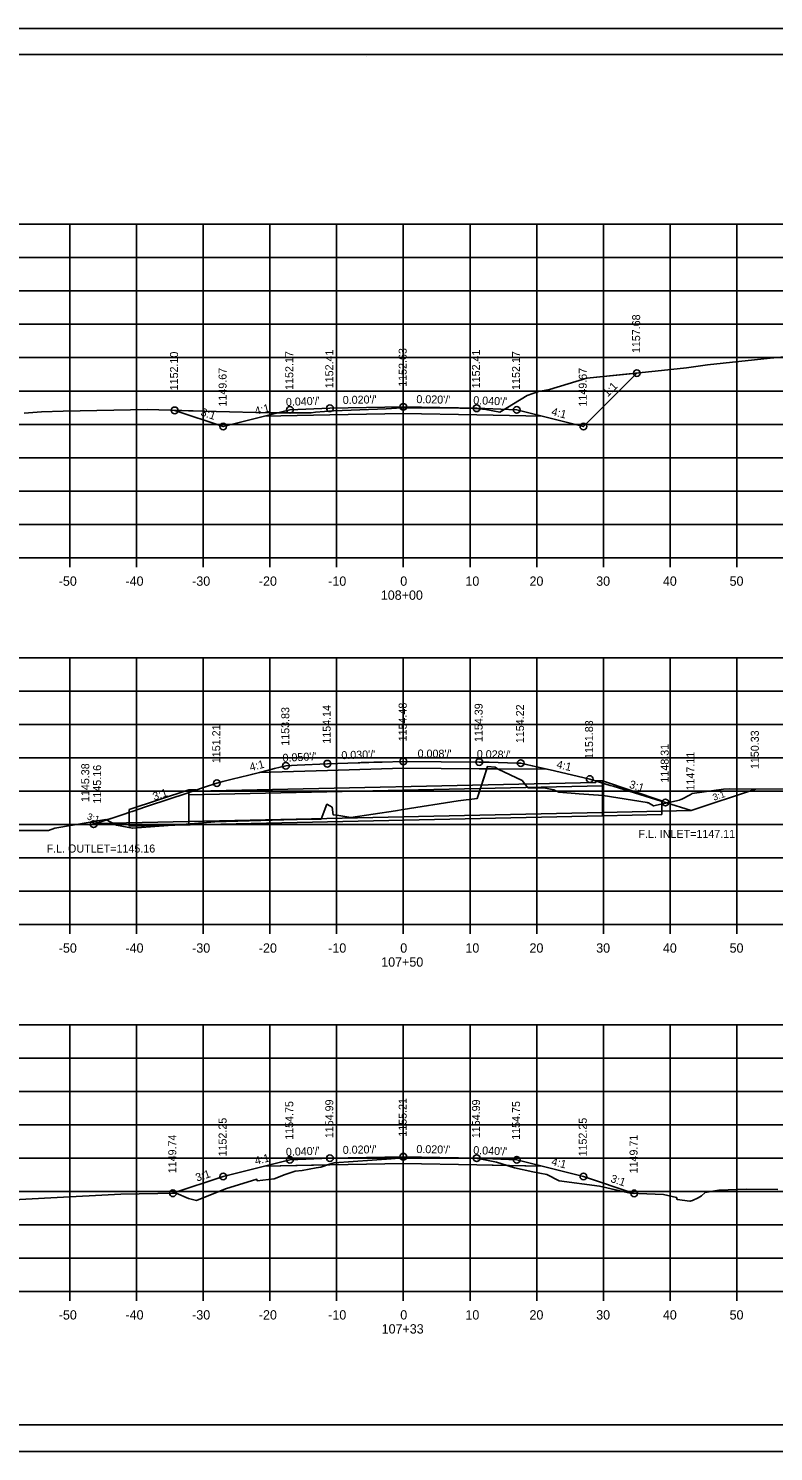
# Model space of a CAD drawing. Extents: x 1368971 to 1374497, y 378717 to 381839.
# Drawn here: x 1374278.1 to 1374389.8, y 380592.1 to 380805.4 of the extents above; entities that cross this region are included whole.
import ezdxf

# ---------------------------------------------------------------- set-up
doc = ezdxf.new("R2010")
doc.units = 0
for name, color, linetype in [('R_Alt Surface', 7, 'Continuous'), ('R_Axis', 7, 'Continuous'), ('R_Axis Annot', 7, 'Continuous'), ('R_Border', 7, 'Continuous'), ('R_Contours', 7, 'Continuous'), ('R_Exist Surface', 7, 'Continuous'), ('R_Fin Surface', 7, 'Continuous'), ('R_Grid', 7, 'Continuous'), ('R_No Plot', 7, 'Continuous'), ('R_Water', 7, 'Continuous'), ('R_Water Annot', 7, 'Continuous'), ('R_Xsect Elev', 7, 'Continuous'), ('R_Xsect Slope', 7, 'Continuous')]:
    doc.layers.add(name, color=color, linetype=linetype)

msp = doc.modelspace()

# ---------------------------------------------------------------- linework, layer by layer
at = {"layer": 'R_Alt Surface'}
for points in [[(1374313.51, 380747.28), (1374323.34, 380747.48), (1374334.34, 380747.7), (1374345.34, 380747.48), (1374355.17, 380747.28)], [(1374312.78, 380693.89), (1374322.95, 380694.2), (1374334.34, 380694.55), (1374345.73, 380694.45), (1374355.9, 380694.37)], [(1374313.51, 380634.86), (1374323.34, 380635.06), (1374334.34, 380635.28), (1374345.34, 380635.06), (1374355.17, 380634.86)]]:
    msp.add_lwpolyline(points, dxfattribs=at)
at = {"layer": 'R_Axis'}
for p, q in [((1374194.34, 380726.07), (1374474.34, 380726.07)), ((1374284.34, 380724.67), (1374284.34, 380726.07)), ((1374294.34, 380724.67), (1374294.34, 380726.07)), ((1374304.34, 380724.67), (1374304.34, 380726.07)), ((1374314.34, 380724.67), (1374314.34, 380726.07)), ((1374324.34, 380724.67), (1374324.34, 380726.07)), ((1374334.34, 380724.67), (1374334.34, 380726.07)), ((1374344.34, 380724.67), (1374344.34, 380726.07)), ((1374354.34, 380724.67), (1374354.34, 380726.07)), ((1374364.34, 380724.67), (1374364.34, 380726.07)), ((1374374.34, 380724.67), (1374374.34, 380726.07)), ((1374384.34, 380724.67), (1374384.34, 380726.07)), ((1374194.34, 380671.07), (1374474.34, 380671.07)), ((1374284.34, 380669.67), (1374284.34, 380671.07)), ((1374294.34, 380669.67), (1374294.34, 380671.07)), ((1374304.34, 380669.67), (1374304.34, 380671.07)), ((1374314.34, 380669.67), (1374314.34, 380671.07)), ((1374324.34, 380669.67), (1374324.34, 380671.07)), ((1374334.34, 380669.67), (1374334.34, 380671.07)), ((1374344.34, 380669.67), (1374344.34, 380671.07)), ((1374354.34, 380669.67), (1374354.34, 380671.07)), ((1374364.34, 380669.67), (1374364.34, 380671.07)), ((1374374.34, 380669.67), (1374374.34, 380671.07)), ((1374384.34, 380669.67), (1374384.34, 380671.07)), ((1374194.34, 380616.07), (1374474.34, 380616.07)), ((1374284.34, 380614.67), (1374284.34, 380616.07)), ((1374294.34, 380614.67), (1374294.34, 380616.07)), ((1374304.34, 380614.67), (1374304.34, 380616.07)), ((1374314.34, 380614.67), (1374314.34, 380616.07)), ((1374324.34, 380614.67), (1374324.34, 380616.07)), ((1374334.34, 380614.67), (1374334.34, 380616.07)), ((1374344.34, 380614.67), (1374344.34, 380616.07)), ((1374354.34, 380614.67), (1374354.34, 380616.07)), ((1374364.34, 380614.67), (1374364.34, 380616.07)), ((1374374.34, 380614.67), (1374374.34, 380616.07)), ((1374384.34, 380614.67), (1374384.34, 380616.07))]:
    msp.add_line(p, q, dxfattribs=at)
at = {"layer": 'R_Border'}
for p, q in [((1374176.34, 380801.53), (1374492.52, 380801.53)), ((1374328.86, 380801.27), (1374328.86, 380801.27)), ((1374328.86, 380801.27), (1374328.86, 380801.27)), ((1374492.52, 380596.07), (1374176.34, 380596.07))]:
    msp.add_line(p, q, dxfattribs=at)
at = {"layer": 'R_Contours'}
for points in [[(1374300.06, 380748.17), (1374306.28, 380747.98), (1374314.22, 380747.79), (1374314.98, 380747.82), (1374320.53, 380747.8), (1374321.17, 380747.89), (1374323.87, 380748.12), (1374331.76, 380748.42), (1374334.11, 380748.54), (1374342.83, 380748.49), (1374345.13, 380748.47), (1374345.66, 380748.38), (1374346.69, 380748.31), (1374348.83, 380747.91), (1374352.9, 380750.4), (1374354.61, 380751), (1374356.26, 380751.32), (1374361.86, 380752.99), (1374369.35, 380753.75), (1374361.34, 380745.74), (1374355.17, 380747.28), (1374345.34, 380747.48), (1374334.34, 380747.7), (1374323.34, 380747.48), (1374313.51, 380747.28), (1374307.34, 380745.74)], [(1374289.84, 380686.77), (1374291.35, 380685.99), (1374293.72, 380685.53), (1374301.76, 380686.15), (1374306.08, 380686.46), (1374318.12, 380686.83), (1374318.21, 380686.84), (1374318.28, 380686.83), (1374318.44, 380686.84), (1374322.01, 380686.89), (1374322.88, 380689.12), (1374323.33, 380688.86), (1374323.69, 380688.67), (1374323.82, 380687.54), (1374324.37, 380687.47), (1374326.47, 380687.11), (1374333.16, 380688.11), (1374334.3, 380688.35), (1374342.57, 380689.64), (1374345.42, 380690), (1374346.87, 380694.45), (1374345.73, 380694.45), (1374334.34, 380694.55), (1374322.95, 380694.2), (1374312.78, 380693.89), (1374311.77, 380693.64), (1374311.16, 380693.48), (1374308.68, 380692.86), (1374307.3, 380692.51), (1374306.95, 380692.42), (1374306.39, 380692.28), (1374304.53, 380691.66), (1374301.49, 380690.65), (1374299.46, 380689.97), (1374295.7, 380688.72), (1374293.68, 380688.05), (1374293.31, 380687.92), (1374292.64, 380687.7), (1374291.15, 380687.2), (1374290.83, 380687.1)], [(1374346.87, 380694.45), (1374346.97, 380694.78), (1374348.13, 380694.7), (1374348.46, 380694.43)], [(1374348.46, 380694.43), (1374348.54, 380694.36), (1374352.14, 380692.67), (1374353.01, 380691.6), (1374355.68, 380691.54), (1374356.89, 380691.29), (1374357.67, 380690.94), (1374360.7, 380690.69), (1374364.31, 380690.43), (1374370.9, 380689.36), (1374371.01, 380689.31), (1374371.11, 380689.31), (1374371.86, 380688.88), (1374373.63, 380689.28), (1374373.63, 380689.37), (1374372.98, 380689.58), (1374365.79, 380691.81), (1374365.36, 380691.95), (1374362.29, 380692.9), (1374357.01, 380694.12), (1374355.9, 380694.37)], [(1374287.91, 380686.12), (1374287.91, 380686.51), (1374289.73, 380686.82), (1374289.84, 380686.77), (1374289.59, 380686.68)], [(1374299.8, 380630.8), (1374300.29, 380630.81), (1374302.15, 380630.04), (1374303.34, 380629.7), (1374307.7, 380631.48), (1374312.4, 380632.91), (1374312.45, 380632.64), (1374314.97, 380632.94), (1374316.63, 380633.61), (1374318.12, 380634.11), (1374319.17, 380634.2), (1374321.29, 380634.59), (1374321.96, 380634.7), (1374322.93, 380635.05), (1374313.51, 380634.86), (1374307.34, 380633.32)], [(1374322.93, 380635.05), (1374323.27, 380635.17), (1374323.95, 380635.37), (1374332.54, 380635.97), (1374334.36, 380636.11), (1374343.37, 380636.07), (1374345.04, 380636.07), (1374346.04, 380635.91), (1374348.33, 380635.47), (1374349.89, 380634.97), (1374345.34, 380635.06), (1374334.34, 380635.28), (1374323.34, 380635.06)], [(1374349.89, 380634.97), (1374351.03, 380634.6), (1374353.76, 380634.01), (1374355.88, 380633.61), (1374357.73, 380632.65), (1374363.73, 380631.86), (1374368.36, 380630.8), (1374368.96, 380630.78), (1374361.34, 380633.32), (1374355.17, 380634.86)]]:
    msp.add_lwpolyline(points, close=True, dxfattribs=at)
at = {"layer": 'R_Exist Surface'}
for points in [[(1374277.49, 380747.74), (1374280.07, 380747.93), (1374283.36, 380748.07), (1374295.99, 380748.29), (1374306.28, 380747.98), (1374314.22, 380747.79), (1374314.98, 380747.82), (1374320.53, 380747.8), (1374321.17, 380747.89), (1374323.87, 380748.12), (1374331.76, 380748.42), (1374334.11, 380748.54), (1374342.83, 380748.49), (1374345.13, 380748.47), (1374345.66, 380748.38), (1374346.69, 380748.31), (1374348.83, 380747.91), (1374352.9, 380750.4), (1374354.61, 380751), (1374356.26, 380751.32), (1374361.86, 380752.99), (1374372.1, 380754.03), (1374376.82, 380754.52), (1374379.93, 380754.97), (1374389.35, 380755.99), (1374404.24, 380757.4)], [(1374275.73, 380685.17), (1374281.14, 380685.19), (1374282.09, 380685.55), (1374289.73, 380686.82), (1374291.35, 380685.99), (1374293.72, 380685.53), (1374301.76, 380686.15), (1374306.08, 380686.46), (1374318.12, 380686.83), (1374318.21, 380686.84), (1374318.28, 380686.83), (1374318.44, 380686.84), (1374322.01, 380686.89), (1374322.88, 380689.12), (1374323.33, 380688.86), (1374323.69, 380688.67), (1374323.82, 380687.54), (1374324.37, 380687.47), (1374326.47, 380687.11), (1374333.16, 380688.11), (1374334.3, 380688.35), (1374342.57, 380689.64), (1374345.42, 380690), (1374346.97, 380694.78), (1374348.13, 380694.7), (1374348.54, 380694.36), (1374352.14, 380692.67), (1374353.01, 380691.6), (1374355.68, 380691.54), (1374356.89, 380691.29), (1374357.67, 380690.94), (1374360.7, 380690.69), (1374364.31, 380690.43), (1374370.9, 380689.36), (1374371.01, 380689.31), (1374371.11, 380689.31), (1374371.86, 380688.88), (1374375.74, 380689.75), (1374375.81, 380689.77), (1374376.12, 380689.89), (1374377.37, 380690.53), (1374377.64, 380690.72), (1374382.36, 380691.4), (1374383.26, 380691.42), (1374391.4, 380691.36)], [(1374264.65, 380629.23), (1374281.5, 380630.12), (1374291.97, 380630.66), (1374300.29, 380630.81), (1374302.15, 380630.04), (1374303.34, 380629.7), (1374307.7, 380631.48), (1374312.4, 380632.91), (1374312.45, 380632.64), (1374314.97, 380632.94), (1374316.63, 380633.61), (1374318.12, 380634.11), (1374319.17, 380634.2), (1374321.29, 380634.59), (1374321.96, 380634.7), (1374323.27, 380635.17), (1374323.95, 380635.37), (1374332.54, 380635.97), (1374334.36, 380636.11), (1374343.37, 380636.07), (1374345.04, 380636.07), (1374346.04, 380635.91), (1374348.33, 380635.47), (1374351.03, 380634.6), (1374353.76, 380634.01), (1374355.88, 380633.61), (1374357.73, 380632.65), (1374363.73, 380631.86), (1374368.36, 380630.8), (1374373.35, 380630.64), (1374375.31, 380630.17), (1374375.41, 380629.85), (1374377.32, 380629.64), (1374377.35, 380629.61), (1374377.52, 380629.66), (1374377.71, 380629.71), (1374378.55, 380630.12), (1374379.03, 380630.42), (1374379.59, 380630.9), (1374381.67, 380631.25), (1374385.85, 380631.4), (1374390.47, 380631.35)]]:
    msp.add_lwpolyline(points, dxfattribs=at)
at = {"layer": 'R_Fin Surface'}
for p, q in [((1374377.49, 380688.18), (1374387.14, 380691.39)), ((1374373.63, 380689.37), (1374377.49, 380688.18)), ((1374288.21, 380686.22), (1374287.5, 380686.45)), ((1374289.59, 380686.68), (1374288.21, 380686.22))]:
    msp.add_line(p, q, dxfattribs=at)
for points in [[(1374300.06, 380748.17), (1374307.34, 380745.74), (1374313.51, 380747.28), (1374317.34, 380748.24), (1374323.34, 380748.48), (1374334.34, 380748.7), (1374345.34, 380748.48), (1374351.34, 380748.24), (1374355.17, 380747.28), (1374361.34, 380745.74), (1374369.35, 380753.75)], [(1374289.59, 380686.68), (1374290.83, 380687.1), (1374291.15, 380687.2), (1374292.64, 380687.7), (1374293.31, 380687.92), (1374293.68, 380688.05), (1374295.7, 380688.72), (1374299.46, 380689.97), (1374301.49, 380690.65), (1374304.53, 380691.66), (1374306.39, 380692.28), (1374306.95, 380692.42), (1374307.3, 380692.51), (1374308.68, 380692.86), (1374311.16, 380693.48), (1374311.77, 380693.64), (1374312.78, 380693.89), (1374313.92, 380694.18), (1374315.02, 380694.46), (1374316.74, 380694.89), (1374318.43, 380694.98), (1374322.95, 380695.2), (1374327.57, 380695.34), (1374327.83, 380695.35), (1374328.03, 380695.36), (1374328.18, 380695.36), (1374328.3, 380695.36), (1374329.19, 380695.39), (1374329.92, 380695.41), (1374331.16, 380695.45), (1374334.34, 380695.55), (1374345.73, 380695.45), (1374347.23, 380695.41), (1374351.32, 380695.3), (1374351.94, 380695.28), (1374353.66, 380694.89), (1374355.9, 380694.37), (1374357.01, 380694.12), (1374362.29, 380692.9), (1374365.36, 380691.95), (1374365.79, 380691.81), (1374372.98, 380689.58), (1374373.63, 380689.37)], [(1374299.8, 380630.8), (1374307.34, 380633.32), (1374313.51, 380634.86), (1374317.34, 380635.82), (1374323.34, 380636.06), (1374334.34, 380636.28), (1374345.34, 380636.06), (1374351.34, 380635.82), (1374355.17, 380634.86), (1374361.34, 380633.32), (1374368.96, 380630.78)]]:
    msp.add_lwpolyline(points, dxfattribs=at)
at = {"layer": 'R_Grid'}
for p, q in [((1374194.34, 380776.07), (1374474.34, 380776.07)), ((1374284.34, 380726.07), (1374284.34, 380776.07)), ((1374294.34, 380726.07), (1374294.34, 380776.07)), ((1374304.34, 380726.07), (1374304.34, 380776.07)), ((1374314.34, 380726.07), (1374314.34, 380776.07)), ((1374324.34, 380726.07), (1374324.34, 380776.07)), ((1374334.34, 380726.07), (1374334.34, 380776.07)), ((1374344.34, 380726.07), (1374344.34, 380776.07)), ((1374354.34, 380726.07), (1374354.34, 380776.07)), ((1374364.34, 380726.07), (1374364.34, 380776.07)), ((1374374.34, 380726.07), (1374374.34, 380776.07)), ((1374384.34, 380726.07), (1374384.34, 380776.07)), ((1374194.34, 380771.07), (1374474.34, 380771.07)), ((1374194.34, 380766.07), (1374474.34, 380766.07)), ((1374194.34, 380761.07), (1374474.34, 380761.07)), ((1374194.34, 380756.07), (1374474.34, 380756.07)), ((1374194.34, 380751.07), (1374474.34, 380751.07)), ((1374194.34, 380746.07), (1374474.34, 380746.07)), ((1374194.34, 380741.07), (1374474.34, 380741.07)), ((1374194.34, 380736.07), (1374474.34, 380736.07)), ((1374194.34, 380731.07), (1374474.34, 380731.07)), ((1374194.34, 380726.07), (1374474.34, 380726.07)), ((1374194.34, 380711.07), (1374474.34, 380711.07)), ((1374284.34, 380671.07), (1374284.34, 380711.07)), ((1374294.34, 380671.07), (1374294.34, 380711.07)), ((1374304.34, 380671.07), (1374304.34, 380711.07)), ((1374314.34, 380671.07), (1374314.34, 380711.07)), ((1374324.34, 380671.07), (1374324.34, 380711.07)), ((1374334.34, 380671.07), (1374334.34, 380711.07)), ((1374344.34, 380671.07), (1374344.34, 380711.07)), ((1374354.34, 380671.07), (1374354.34, 380711.07)), ((1374364.34, 380671.07), (1374364.34, 380711.07)), ((1374374.34, 380671.07), (1374374.34, 380711.07)), ((1374384.34, 380671.07), (1374384.34, 380711.07)), ((1374194.34, 380706.07), (1374474.34, 380706.07)), ((1374194.34, 380701.07), (1374474.34, 380701.07)), ((1374194.34, 380696.07), (1374474.34, 380696.07)), ((1374194.34, 380691.07), (1374474.34, 380691.07)), ((1374194.34, 380686.07), (1374474.34, 380686.07)), ((1374194.34, 380681.07), (1374474.34, 380681.07)), ((1374194.34, 380676.07), (1374474.34, 380676.07)), ((1374194.34, 380671.07), (1374474.34, 380671.07)), ((1374194.34, 380656.07), (1374474.34, 380656.07)), ((1374284.34, 380616.07), (1374284.34, 380656.07)), ((1374294.34, 380616.07), (1374294.34, 380656.07)), ((1374304.34, 380616.07), (1374304.34, 380656.07)), ((1374314.34, 380616.07), (1374314.34, 380656.07)), ((1374324.34, 380616.07), (1374324.34, 380656.07)), ((1374334.34, 380616.07), (1374334.34, 380656.07)), ((1374344.34, 380616.07), (1374344.34, 380656.07)), ((1374354.34, 380616.07), (1374354.34, 380656.07)), ((1374364.34, 380616.07), (1374364.34, 380656.07)), ((1374374.34, 380616.07), (1374374.34, 380656.07)), ((1374384.34, 380616.07), (1374384.34, 380656.07)), ((1374194.34, 380651.07), (1374474.34, 380651.07)), ((1374194.34, 380646.07), (1374474.34, 380646.07)), ((1374194.34, 380641.07), (1374474.34, 380641.07)), ((1374194.34, 380636.07), (1374474.34, 380636.07)), ((1374194.34, 380631.07), (1374474.34, 380631.07)), ((1374194.34, 380626.07), (1374474.34, 380626.07)), ((1374194.34, 380621.07), (1374474.34, 380621.07)), ((1374194.34, 380616.07), (1374474.34, 380616.07))]:
    msp.add_line(p, q, dxfattribs=at)
at = {"layer": 'R_No Plot'}
for p, q in [((1374163.94, 380805.42), (1374497.27, 380805.42)), ((1374163.94, 380592.09), (1374497.27, 380592.09))]:
    msp.add_line(p, q, dxfattribs=at)
for points in [[(1374163.93, 380805.42), (1374497.27, 380805.42), (1374497.27, 380592.08), (1374163.93, 380592.08)], [(1374410.26, 380801.53), (1374410.26, 380791.65), (1374445.99, 380791.65), (1374445.99, 380788.73), (1374469.19, 380788.73), (1374469.19, 380765.51), (1374492.52, 380765.51), (1374492.52, 380596.07), (1374176.34, 380596.07), (1374176.34, 380801.53)]]:
    msp.add_lwpolyline(points, close=True, dxfattribs=at)
for centre in [(1374369.35, 380753.75), (1374300.06, 380748.17), (1374317.34, 380748.24), (1374323.34, 380748.48), (1374334.34, 380748.7), (1374345.34, 380748.48), (1374351.34, 380748.24), (1374307.34, 380745.74), (1374361.34, 380745.74), (1374316.74, 380694.89), (1374322.95, 380695.2), (1374334.34, 380695.55), (1374345.73, 380695.45), (1374351.94, 380695.28), (1374306.39, 380692.28), (1374362.29, 380692.9), (1374373.63, 380689.37), (1374287.91, 380686.12), (1374317.34, 380635.82), (1374323.34, 380636.06), (1374334.34, 380636.28), (1374345.34, 380636.06), (1374351.34, 380635.82), (1374307.34, 380633.32), (1374361.34, 380633.32), (1374299.8, 380630.8), (1374368.96, 380630.78)]:
    msp.add_circle(centre, 0.5, dxfattribs=at)
at = {"layer": 'R_Water'}
for p, q in [((1374364.19, 380692.63), (1374364.19, 380687.38)), ((1374364.19, 380692.63), (1374373.12, 380689.65)), ((1374302.19, 380691.29), (1374293.25, 380688.31)), ((1374364.19, 380691.88), (1374302.19, 380690.54)), ((1374302.19, 380686.04), (1374302.19, 380691.29)), ((1374363.19, 380692.36), (1374303.19, 380691.06)), ((1374293.25, 380685.84), (1374293.25, 380688.31)), ((1374364.19, 380687.88), (1374377.49, 380688.18)), ((1374373.12, 380687.58), (1374373.12, 380689.65)), ((1374302.19, 380686.54), (1374288.21, 380686.22)), ((1374364.19, 380687.38), (1374293.25, 380685.84)), ((1374364.19, 380687.88), (1374302.19, 380686.54)), ((1374364.19, 380687.38), (1374373.12, 380687.58))]:
    msp.add_line(p, q, dxfattribs=at)
for points in [[(1374364.19, 380692.63), (1374363.19, 380692.63), (1374363.19, 380692.36)], [(1374302.19, 380691.29), (1374303.19, 380691.29), (1374303.19, 380691.06)]]:
    msp.add_lwpolyline(points, dxfattribs=at)

# ---------------------------------------------------------------- texts
at = {"layer": 'R_Axis Annot'}
for s, p in [('-50', (1374282.68, 380721.87)), ('-40', (1374292.68, 380721.87)), ('-30', (1374302.68, 380721.87)), ('-20', (1374312.68, 380721.87)), ('-10', (1374323.08, 380721.87)), ('0', (1374333.88, 380721.87)), ('10', (1374343.65, 380721.87)), ('20', (1374353.26, 380721.87)), ('30', (1374363.26, 380721.87)), ('40', (1374373.26, 380721.87)), ('50', (1374383.26, 380721.87)), ('108+00', (1374330.97, 380719.77)), ('-50', (1374282.68, 380666.87)), ('-40', (1374292.68, 380666.87)), ('-30', (1374302.68, 380666.87)), ('-20', (1374312.68, 380666.87)), ('-10', (1374323.08, 380666.87)), ('0', (1374333.88, 380666.87)), ('10', (1374343.65, 380666.87)), ('20', (1374353.26, 380666.87)), ('30', (1374363.26, 380666.87)), ('40', (1374373.26, 380666.87)), ('50', (1374383.26, 380666.87)), ('107+50', (1374331.03, 380664.77)), ('-50', (1374282.68, 380611.87)), ('-40', (1374292.68, 380611.87)), ('-30', (1374302.68, 380611.87)), ('-20', (1374312.68, 380611.87)), ('-10', (1374323.08, 380611.87)), ('0', (1374333.88, 380611.87)), ('10', (1374343.65, 380611.87)), ('20', (1374353.26, 380611.87)), ('30', (1374363.26, 380611.87)), ('40', (1374373.26, 380611.87)), ('50', (1374383.26, 380611.87)), ('107+33', (1374331.09, 380609.77))]:
    msp.add_text(s, height=1.4, dxfattribs=at).set_placement(p)
at = {"layer": 'R_Water Annot'}
for s, p in [('F.L. INLET=1147.11', (1374369.59, 380684.08)), ('F.L. OUTLET=1145.16', (1374280.86, 380681.88))]:
    msp.add_text(s, height=1.2, dxfattribs=at).set_placement(p)
at = {"layer": 'R_Xsect Elev'}
for s, p in [('1157.68', (1374369.85, 380756.75)), ('1152.10', (1374300.56, 380751.17)), ('1152.17', (1374317.84, 380751.24)), ('1152.41', (1374323.84, 380751.48)), ('1152.63', (1374334.84, 380751.7)), ('1152.41', (1374345.84, 380751.48)), ('1152.17', (1374351.84, 380751.24)), ('1149.67', (1374307.84, 380748.74)), ('1149.67', (1374361.84, 380748.74)), ('1153.83', (1374317.24, 380697.89)), ('1154.14', (1374323.45, 380698.2)), ('1154.48', (1374334.84, 380698.55)), ('1154.39', (1374346.23, 380698.45)), ('1154.22', (1374352.44, 380698.28)), ('1151.21', (1374306.89, 380695.28)), ('1151.83', (1374362.79, 380695.9)), ('1150.33', (1374387.64, 380694.39)), ('1148.31', (1374374.13, 380692.37)), ('1147.11', (1374377.99, 380691.18)), ('1145.38', (1374287.25, 380689.45)), ('1145.16', (1374289.03, 380689.22)), ('1154.75', (1374317.84, 380638.82)), ('1154.99', (1374323.84, 380639.06)), ('1155.21', (1374334.84, 380639.28)), ('1154.99', (1374345.84, 380639.06)), ('1154.75', (1374351.84, 380638.82)), ('1152.25', (1374307.84, 380636.32)), ('1152.25', (1374361.84, 380636.32)), ('1149.74', (1374300.3, 380633.8)), ('1149.71', (1374369.46, 380633.78))]:
    msp.add_text(s, height=1.2, rotation=90, dxfattribs=at).set_placement(p)
at = {"layer": 'R_Xsect Slope'}
for s, height, rotation, p in [('1:1', 1.2, 45, (1374364.99, 380750.1)), ("0.040'/'", 1.2, 2.2906, (1374316.76, 380748.82)), ("0.020'/'", 1.2, 1.1458, (1374325.27, 380749.12)), ("0.020'/'", 1.2, 358.8542, (1374336.29, 380749.26)), ("0.040'/'", 1.2, 357.7094, (1374344.81, 380749.1)), ('3:1', 1.2, 341.5651, (1374303.86, 380747.43)), ('4:1', 1.2, 14.0362, (1374312.22, 380747.47)), ('4:1', 1.2, 345.9638, (1374356.46, 380747.47)), ("0.050'/'", 1.2, 2.8471, (1374316.26, 380695.47)), ("0.030'/'", 1.2, 1.742, (1374325.07, 380695.87)), ("0.008'/'", 1.2, 359.5288, (1374336.48, 380696.13)), ("0.028'/'", 1.2, 358.4223, (1374345.34, 380696.07)), ('4:1', 1.2, 14.1751, (1374311.44, 380694.07)), ('4:1', 1.2, 347.0262, (1374357.23, 380694.58)), ('3:1', 1.2, 342.7305, (1374368.11, 380691.61)), ('3:1', 1.2, 18.4213, (1374296.99, 380689.67)), ('3:1', 1, 18.4213, (1374380.92, 380689.64)), ('3:1', 1, 342.7305, (1374286.85, 380686.87)), ("0.040'/'", 1.2, 2.2906, (1374316.76, 380636.39)), ("0.020'/'", 1.2, 1.1458, (1374325.27, 380636.7)), ("0.020'/'", 1.2, 358.8542, (1374336.29, 380636.84)), ("0.040'/'", 1.2, 357.7094, (1374344.81, 380636.68)), ('4:1', 1.2, 14.0362, (1374312.22, 380635.05)), ('4:1', 1.2, 345.9638, (1374356.46, 380635.05)), ('3:1', 1.2, 18.4349, (1374303.41, 380632.54)), ('3:1', 1.2, 341.5651, (1374365.31, 380632.52))]:
    msp.add_text(s, height=height, rotation=rotation, dxfattribs=at).set_placement(p)

doc.saveas('drawing.dxf')
